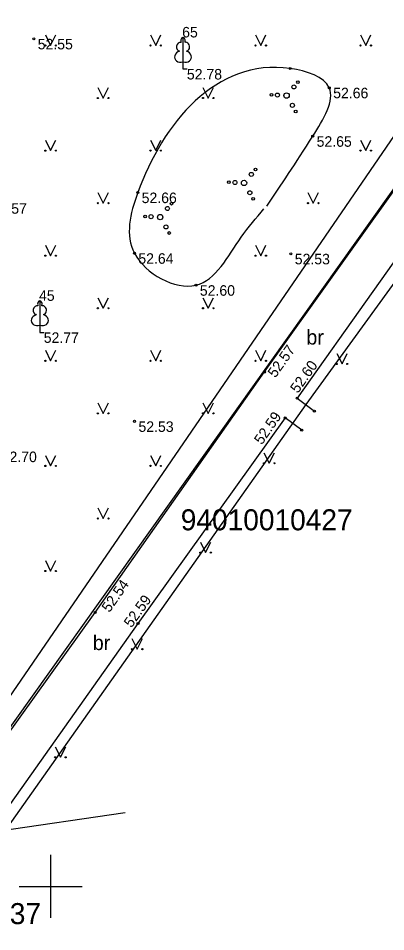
# Model space of a CAD drawing. Extents: x 619806 to 620082, y 405176 to 405386.
# Drawn here: x 619998.46 to 620015.95, y 405197.84 to 405241.29 of the extents above; entities that cross this region are included whole.
import ezdxf

# ---------------------------------------------------------------- set-up
doc = ezdxf.new("R2010")
doc.units = 0
for name, color, linetype in [('APGR_SARK_####_####_#', 7, 'Continuous'), ('CELI_CMAL_####_####_#', 7, 'Continuous'), ('CELI_CSEG_####_TKST_#', 7, 'Continuous'), ('GEOD_ELEM_####_####_#', 7, 'Continuous'), ('RAMI_UZMR_####_####_#', 7, 'Continuous'), ('RELJ_AATZ_####_TKST_#', 7, 'Continuous'), ('RELJ_ELEM_####_####_#', 7, 'Continuous'), ('ROBZ_PROJ_####_####_#', 7, 'Continuous'), ('ROBZ_PROJ_####_TKST_#', 7, 'Continuous'), ('ROBZ_UZMR_####_####_#', 7, 'Continuous'), ('TERT_DIAM_####_TKST_#', 7, 'Continuous'), ('TERT_ELEM_####_####_#', 7, 'Continuous'), ('TERT_KONT_####_####_#', 7, 'Continuous')]:
    doc.layers.add(name, color=color, linetype=linetype)

msp = doc.modelspace()

# ---------------------------------------------------------------- linework, layer by layer
at = {"layer": 'APGR_SARK_####_####_#'}
msp.add_lwpolyline([(619976.198, 405343.424), (619987.786, 405326.116), (620001.138, 405307.928), (620014.265, 405290.061), (620015.405, 405288.784), (620016.767, 405287.746), (620041.487, 405272.379), (619990.053, 405197.403), (619990.053, 405197.403)], dxfattribs=at)
at = {"layer": 'CELI_CMAL_####_####_#'}
for points in [[(620047.008, 405270.595), (620045.914, 405271.411), (620038.491, 405260.919), (620032.163, 405251.981), (620025.649, 405242.786), (620018.938, 405233.375), (620011.736, 405223.226), (620012.557, 405222.608)], [(619978.832, 405249.941), (619981.369, 405226.774), (619981.804, 405224.124), (619982.441, 405217.773), (619982.996, 405213.675), (619983.965, 405205.418), (619983.685, 405203.225), (619985.778, 405202.103), (619986.248, 405201.889), (619987.106, 405201.651), (619987.96, 405201.56), (619988.713, 405201.545), (619992.1, 405202.316), (619994.967, 405203.071), (620002.119, 405213.03), (620010.184, 405224.469), (620017.253, 405234.372), (620024.304, 405244.304)], [(620011.952, 405221.698), (620011.164, 405222.283), (620004.158, 405212.507), (619996.695, 405201.997), (619996.454, 405201.7), (619996.147, 405201.443), (619995.7, 405201.193), (619995.235, 405201.037), (619990.124, 405199.688), (619985.9, 405199.485), (619981.548, 405199.473), (619981.112, 405199.297)]]:
    msp.add_lwpolyline(points, dxfattribs=at)
at = {"layer": 'GEOD_ELEM_####_####_#'}
for p, q in [((620000, 405201.5), (620000, 405200)), ((619998.5, 405200), (620000, 405200)), ((620000, 405200), (620000, 405198.5)), ((620000, 405200), (620001.5, 405200))]:
    msp.add_line(p, q, dxfattribs=at)
at = {"layer": 'RAMI_UZMR_####_####_#'}
msp.add_lwpolyline([(619874.687, 405324.979), (619926.719, 405349.544), (619966.669, 405369.042), (620021.738, 405292.03), (620049.703, 405275.476), (620026.189, 405242.287), (620012.147, 405222.917), (619996.603, 405200.928), (619989.997, 405199.173), (619982.328, 405199.155), (619922.669, 405233.014), (619882.137, 405255.756), (619859.084, 405268.056), (619820.646, 405290.715), (619813.744, 405295.206), (619820.645, 405298.752)], close=True, dxfattribs=at)
at = {"layer": 'RELJ_ELEM_####_####_#'}
for centre in [(619999.198, 405240.314), (620011.401, 405238.905), (620013.265, 405237.989), (620012.477, 405235.682), (620004.147, 405233.002), (620003.99, 405230.116), (620011.436, 405230.089), (620006.918, 405228.596), (620010.184, 405224.469), (620011.736, 405223.226), (620012.557, 405222.608), (620003.995, 405222.119), (620011.164, 405222.283), (620011.952, 405221.698), (620002.119, 405213.03), (620004.158, 405212.507)]:
    msp.add_circle(centre, 0.05, dxfattribs=at)
at = {"layer": 'ROBZ_PROJ_####_####_#'}
msp.add_line((619994.191, 405202.148), (620003.548, 405203.517), dxfattribs=at)
at = {"layer": 'ROBZ_UZMR_####_####_#'}
msp.add_line((620044.084, 405272.127), (619994.191, 405202.148), dxfattribs=at)
at = {"layer": 'TERT_ELEM_####_####_#'}
for p, q in [((619999.75, 405240.5), (620000, 405240)), ((620000, 405240), (620000.25, 405240.5)), ((620004.75, 405240.5), (620005, 405240)), ((620005, 405240), (620005.25, 405240.5)), ((620009.75, 405240.5), (620010, 405240)), ((620010, 405240), (620010.25, 405240.5)), ((620014.75, 405240.5), (620015, 405240)), ((620015, 405240), (620015.25, 405240.5)), ((620006.301, 405239.229), (620006.301, 405238.882)), ((620006.301, 405238.882), (620006.501, 405238.882)), ((620002.25, 405238), (620002.5, 405237.5)), ((620002.5, 405237.5), (620002.75, 405238)), ((620007.25, 405238), (620007.5, 405237.5)), ((620007.5, 405237.5), (620007.75, 405238)), ((619999.75, 405235.5), (620000, 405235)), ((620000, 405235), (620000.25, 405235.5)), ((620004.75, 405235.5), (620005, 405235)), ((620005, 405235), (620005.25, 405235.5)), ((620014.75, 405235.5), (620015, 405235)), ((620015, 405235), (620015.25, 405235.5)), ((620002.25, 405233), (620002.5, 405232.5)), ((620002.5, 405232.5), (620002.75, 405233)), ((620012.25, 405233), (620012.5, 405232.5)), ((620012.5, 405232.5), (620012.75, 405233)), ((619999.75, 405230.5), (620000, 405230)), ((620000, 405230), (620000.25, 405230.5)), ((620009.75, 405230.5), (620010, 405230)), ((620010, 405230), (620010.25, 405230.5)), ((620002.25, 405228), (620002.5, 405227.5)), ((620002.5, 405227.5), (620002.75, 405228)), ((620007.25, 405228), (620007.5, 405227.5)), ((620007.5, 405227.5), (620007.75, 405228)), ((619999.486, 405226.7), (619999.486, 405226.353)), ((619999.486, 405226.353), (619999.686, 405226.353)), ((619999.75, 405225.5), (620000, 405225)), ((620000, 405225), (620000.25, 405225.5)), ((620004.75, 405225.5), (620005, 405225)), ((620005, 405225), (620005.25, 405225.5)), ((620009.75, 405225.5), (620010, 405225)), ((620010, 405225), (620010.25, 405225.5)), ((620013.621, 405225.351), (620013.871, 405224.851)), ((620013.871, 405224.851), (620014.121, 405225.351)), ((620002.25, 405223), (620002.5, 405222.5)), ((620002.5, 405222.5), (620002.75, 405223)), ((620007.25, 405223), (620007.5, 405222.5)), ((620007.5, 405222.5), (620007.75, 405223)), ((619999.75, 405220.5), (620000, 405220)), ((620000, 405220), (620000.25, 405220.5)), ((620004.75, 405220.5), (620005, 405220)), ((620005, 405220), (620005.25, 405220.5)), ((620010.154, 405220.627), (620010.404, 405220.127)), ((620010.404, 405220.127), (620010.654, 405220.627)), ((620002.25, 405218), (620002.5, 405217.5)), ((620002.5, 405217.5), (620002.75, 405218)), ((620007.127, 405216.377), (620007.377, 405215.877)), ((620007.377, 405215.877), (620007.627, 405216.377)), ((619999.75, 405215.5), (620000, 405215)), ((620000, 405215), (620000.25, 405215.5)), ((620003.866, 405211.783), (620004.116, 405211.283)), ((620004.116, 405211.283), (620004.366, 405211.783)), ((620000.217, 405206.64), (620000.467, 405206.14)), ((620000.467, 405206.14), (620000.717, 405206.64))]:
    msp.add_line(p, q, dxfattribs=at)
for points in [[(620006.301, 405240.382), (620006.301, 405239.229)], [(620006.391, 405240.15), (620006.39, 405240.151)], [(619999.486, 405227.853), (619999.486, 405226.7)], [(619999.576, 405227.621), (619999.575, 405227.622)]]:
    msp.add_lwpolyline(points, dxfattribs=at)
for centre, radius in [((619999.75, 405240), 0.028), ((620000.25, 405240), 0.0263), ((620004.75, 405240), 0.028), ((620005.25, 405240), 0.0263), ((620009.75, 405240), 0.028), ((620010.25, 405240), 0.0263), ((620014.75, 405240), 0.028), ((620015.25, 405240), 0.0263), ((620011.579, 405238.027), 0.096), ((620011.775, 405238.258), 0.064), ((620010.513, 405237.653), 0.064), ((620010.797, 405237.64), 0.096), ((620011.231, 405237.619), 0.128), ((620002.25, 405237.5), 0.028), ((620002.75, 405237.5), 0.0263), ((620007.25, 405237.5), 0.028), ((620007.75, 405237.5), 0.0263), ((620011.508, 405237.152), 0.096), ((620011.665, 405236.863), 0.064), ((619999.75, 405235), 0.028), ((620000.25, 405235), 0.0263), ((620004.75, 405235), 0.028), ((620005.25, 405235), 0.0263), ((620014.75, 405235), 0.028), ((620015.25, 405235), 0.0263), ((620009.751, 405234.099), 0.064), ((620009.554, 405233.868), 0.096), ((620008.488, 405233.494), 0.064), ((620008.773, 405233.481), 0.096), ((620009.207, 405233.46), 0.128), ((620009.483, 405232.993), 0.096), ((620002.25, 405232.5), 0.028), ((620002.75, 405232.5), 0.0263), ((620005.757, 405232.475), 0.064), ((620009.641, 405232.704), 0.064), ((620012.25, 405232.5), 0.028), ((620012.75, 405232.5), 0.0263), ((620004.779, 405231.857), 0.096), ((620005.213, 405231.836), 0.128), ((620005.56, 405232.244), 0.096), ((620004.494, 405231.87), 0.064), ((620005.489, 405231.369), 0.096), ((620005.647, 405231.08), 0.064), ((619999.75, 405230), 0.028), ((620000.25, 405230), 0.0263), ((620009.75, 405230), 0.028), ((620010.25, 405230), 0.0263), ((620002.25, 405227.5), 0.028), ((620002.75, 405227.5), 0.0263), ((620007.25, 405227.5), 0.028), ((620007.75, 405227.5), 0.0263), ((619999.75, 405225), 0.028), ((620000.25, 405225), 0.0263), ((620004.75, 405225), 0.028), ((620005.25, 405225), 0.0263), ((620009.75, 405225), 0.028), ((620010.25, 405225), 0.0263), ((620013.62, 405224.85), 0.028), ((620014.12, 405224.85), 0.0263), ((620002.25, 405222.5), 0.028), ((620002.75, 405222.5), 0.0263), ((620007.25, 405222.5), 0.028), ((620007.75, 405222.5), 0.0263), ((619999.75, 405220), 0.028), ((620000.25, 405220), 0.0263), ((620004.75, 405220), 0.028), ((620005.25, 405220), 0.0263), ((620010.154, 405220.126), 0.028), ((620010.654, 405220.126), 0.0263), ((620002.25, 405217.5), 0.028), ((620002.75, 405217.5), 0.0263), ((620007.127, 405215.876), 0.028), ((620007.627, 405215.876), 0.0263), ((619999.75, 405215), 0.028), ((620000.25, 405215), 0.0263), ((620003.866, 405211.282), 0.028), ((620004.366, 405211.282), 0.0263), ((620000.216, 405206.14), 0.028), ((620000.716, 405206.14), 0.0263)]:
    msp.add_circle(centre, radius, dxfattribs=at)
for centre, major_axis, ratio, start_param, end_param in [((620006.301, 405240.232), (0, -0.15), 0.707107, 3.14537, 5.287485), ((620006.301, 405240.232), (0, -0.15), 0.707107, 0.995701, 3.137816), ((620006.173, 405239.937), (-0.039, -0.212), 0.861323, 3.141593, 6.283185), ((620006.429, 405239.937), (0.039, -0.212), 0.861323, 0, 3.141593), ((620006.211, 405239.475), (0.307, 0.095), 0.814445, 1.570796, 4.752015), ((620006.391, 405239.475), (-0.307, 0.095), 0.814445, 1.531171, 4.712389), ((619999.358, 405227.408), (-0.039, -0.212), 0.861323, 3.141593, 6.283185), ((619999.486, 405227.703), (0, -0.15), 0.707107, 3.14537, 5.287485), ((619999.486, 405227.703), (0, -0.15), 0.707107, 0.995701, 3.137816), ((619999.614, 405227.408), (0.039, -0.212), 0.861323, 0, 3.141593), ((619999.396, 405226.946), (0.307, 0.095), 0.814445, 1.570796, 4.752015), ((619999.576, 405226.946), (-0.307, 0.095), 0.814445, 1.531171, 4.712389)]:
    msp.add_ellipse(centre, major_axis=major_axis, ratio=ratio, start_param=start_param, end_param=end_param, dxfattribs=at)
at = {"layer": 'TERT_KONT_####_####_#'}
msp.add_spline([(620010.289, 405232.353), (620012.477, 405235.682), (620013.265, 405237.989), (620011.401, 405238.905), (620004.147, 405233.002), (620003.99, 405230.116), (620006.918, 405228.596), (620009.071, 405230.879), (620010.154, 405232.222)], degree=3, dxfattribs=at)

# ---------------------------------------------------------------- texts
at = {"layer": 'CELI_CSEG_####_TKST_#'}
for p in [(620012.174, 405225.773), (620002.007, 405211.239)]:
    msp.add_text('br', height=0.7, dxfattribs=at).set_placement(p)
at = {"layer": 'RELJ_AATZ_####_TKST_#'}
for s, p in [(' 52.55', (619999.198, 405239.814)), (' 52.78', (620006.301, 405238.382)), (' 52.66', (620013.265, 405237.489)), (' 52.65', (620012.477, 405235.182)), (' 52.66', (620004.147, 405232.502)), (' 52.57', (619997.01, 405231.996)), (' 52.64', (620003.99, 405229.616)), (' 52.53', (620011.436, 405229.589)), (' 52.60', (620006.918, 405228.096)), (' 52.77', (619999.486, 405225.853)), (' 52.53', (620003.995, 405221.619)), (' 52.70', (619997.483, 405220.182))]:
    msp.add_text(s, height=0.5, dxfattribs=at).set_placement(p)
for s, rotation, p in [(' 52.57', 54.4798, (620010.591, 405224.009)), (' 52.60', 54.6395, (620011.663, 405223.271)), (' 52.59', 55.2596, (620009.951, 405220.824)), (' 52.54', 54.8145, (620002.69, 405212.845)), (' 52.59', 54.3726, (620003.74, 405212.12))]:
    msp.add_text(s, height=0.5, rotation=rotation, dxfattribs=at).set_placement(p)
at = {"layer": 'ROBZ_PROJ_####_TKST_#'}
for s, p in [('94010010427', (620006.195, 405216.936)), ('94010010837', (619991.362, 405198.203))]:
    msp.add_text(s, height=1, dxfattribs=at).set_placement(p)
at = {"layer": 'TERT_DIAM_####_TKST_#'}
for s, p in [(' 65', (620006.076, 405240.382)), (' 45', (619999.261, 405227.853))]:
    msp.add_text(s, height=0.5, dxfattribs=at).set_placement(p)

doc.saveas('drawing.dxf')
